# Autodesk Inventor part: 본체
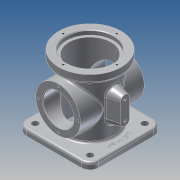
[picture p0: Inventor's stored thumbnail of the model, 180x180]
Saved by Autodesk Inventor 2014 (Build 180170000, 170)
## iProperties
Created: 2021-03
Part Number: 본체
Material: 알루미늄 6061
Document SubType Name: Modeling
Designer: kb542
Density: 2.71 g/cm^3
Appearance: 알루미늄 - 평지
Mass: 834.797 g
Surface Area: 861.783 cm^2
Volume: 308.043 cm^3
Author: kb542
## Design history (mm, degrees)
sketch "스케치1"
  geometry: L1 (0, 0)-(0, -111); L2 (0, 0)-(49, 0); L3 (49, 0)-(49, -13); L4 (49, -13)-(38, -13); L5 (38, -13)-(38, -111); L6 (38, -111)-(0, -111)
  constraints: 12 end point, 3 parallel, 2 perpendicular, 1 vertical
  dimensions: "d0" = 111 distance between parallel lines of L6 L2; "d1" = 76 diameter of L5 L1; "d2" = 98 diameter of L3 L1; "d3" = 13 distance between parallel lines of L4 L2
revolve "회전1" sketch "스케치1" stored, may be unused: angle "d4" = 90 deg
sketch "스케치2"
  geometry: L1 (-57, 57)-(57, 57); L2 (57, 57)-(57, -57); L3 (57, -57)-(-57, -57); L4 (-57, -57)-(-57, 57); C1 r 38 at (0, 0) reference; 2 further points
  constraints: 8 end point, 2 midpoint, 2 parallel, 1 horizontal, 1 horizontal alignment, 1 perpendicular, 1 vertical alignment
  dimensions: "d5" = 114 distance of L1.start L1.end; "d6" = 114 distance of L1.end L2.end
extrude "돌출1" join sketch "스케치2" distance "d7" = 10; taper "d8" = 0 deg
sketch "스케치3"
  geometry: L1 (-49, 0)-(49, 0) reference; L2 (57, -111)-(-57, -111) reference; L3 (0, 0)-(0, -111); L4 (0, 0)-(37, 0); L5 (37, 0)-(37, -7); L6 (37, -7)-(33, -7); L7 (33, -7)-(33, -111); L8 (33, -111)-(0, -111)
  constraints: 12 end point, 2 perpendicular, 2 point on line, 1 collinear, 1 midpoint, 1 parallel
  dimensions: "d9" = 74 diameter of L5 L3; "d10" = 66 diameter of L7 L3; "d11" = 7 distance between parallel lines of L1 L6
revolve "회전2" sketch "스케치3" stored, may be unused: angle "d12" = 90 deg
node "작업 평면1"
sketch "스케치4"
  geometry: L1 (0, 49)-(0, -49) reference; L2 (-111, 57)-(-111, -57) reference; L3 (-13, 38)-(-101, 38) reference; L4 (-13, -38)-(-101, -38) reference; L5 (-57, 38)-(-57, -38); L6 (0, 0)-(-111, 0); C1 r 35 at (-57, 0)
  constraints: 4 end point, 4 midpoint, 1 centre point, 1 perpendicular, 1 point on line
  dimensions: "d14" = 54 distance between parallel lines of L2 L5; "d15" = 70 diameter of C1
extrude "돌출2" join sketch "스케치4" stored distance "d16" = 10; taper "d17" = 0 deg
sketch "스케치5"
  geometry: C1 r 35 at (0, 0) reference; C2 r 24 at (0, 0); 1 further point
  constraints: 1 centre point, 1 coincident
  dimensions: "d18" = 48 diameter of C2
extrude "돌출3" cut sketch "스케치5" stored distance "d19" = 10; taper "d20" = 0 deg
sketch "스케치6" dims "d21" = 62
  geometry: C1 r 24 at (0, 0) reference; C2 r 35 at (0, 0) reference; 6 further points
  constraints: 2 vertical alignment, 1 coincident, 7 other
  dimensions: "d24" = 360 deg dimension on C1.centre point (0, 31) (derived)
hole "구멍1" sketch "스케치6" at (0, 31), (-31, 0), (0, -31), (31, 0) diameter "d26" = 3.242; stored, may be unused: countersink angle "d30" = 90 deg, drill point angle "d32" = 118 deg; dims "d27" = 6, "d28" = 4, "d29" = 2, "d31" = 8
fillet "모깎기1" dims "d33" = 14
sketch "스케치7"
  geometry: A1 r 14 centre (43, 43) between (57, 43) and (43, 57) reference; A2 r 14 centre (-43, 43) between (-43, 57) and (-57, 43) reference; A3 r 14 centre (-43, -43) between (-57, -43) and (-43, -57) reference; A4 r 14 centre (43, -43) between (43, -57) and (57, -43) reference; 4 further points
  constraints: 4 coincident
hole "구멍2" sketch "스케치7" at (-43, 43), (43, 43), (43, -43), (-43, -43) diameter "d34" = 10; stored, may be unused: countersink angle "d38" = 90 deg, drill point angle "d40" = 0 deg; dims "d35" = 6, "d36" = 4, "d37" = 2, "d39" = 8
node "작업 평면3"
sketch "스케치8"
  geometry: L1 (-50, -22)-(-50, -92) reference; L2 (50, -22)-(50, -92) reference; L3 (-50, -57)-(50, -57); L4 (0, -41)-(0, -70); L5 (-7, -41)-(-7, -70); L6 (7, -70)-(7, -41); A1 r 7 centre (0, -41) between (7, -41) and (-7, -41); A2 r 7 centre (0, -70) between (-7, -70) and (7, -70); 3 further points
  constraints: 10 end point, 4 midpoint, 4 point on circle, 4 tangent, 2 centre point, 1 parallel, 1 perpendicular, 1 vertical alignment
  dimensions: "d42" = 43 dimension on A2 A1; "d43" = 14 distance between parallel lines of L5 L6; "d44" = 20 dimension on A2 L3
extrude "돌출4" join sketch "스케치8" stored distance "d45" = 10; taper "d46" = 15 deg
sketch "스케치9"
  geometry: A1 r 7 centre (0, -70) between (-7, -70) and (7, -70) reference; A2 r 7 centre (0, -41) between (7, -41) and (-7, -41) reference; 3 further points
  constraints: 2 coincident
hole "구멍3" sketch "스케치9" at (0, -41), (0, -70) diameter "d47" = 4.134; stored, may be unused: countersink angle "d51" = 90 deg, drill point angle "d53" = 118 deg; dims "d48" = 8, "d49" = 4, "d50" = 2, "d52" = 10
sketch "스케치10"
  geometry: C1 r 38 at (0, 0) reference; C2 r 50 at (0, 0)
  constraints: 1 centre point, 1 coincident, 1 other
  dimensions: "d54" = 100 diameter of C2
feature "엠보싱1" sketch "스케치10" dims "d0" = 111, "d1" = 76, "d2" = 98, "d3" = 13, "d55" = 1, "d56" = 0
fillet "모깎기2" dims "d57" = 3
chamfer "모따기1" distance "d58" = 1; stored, may be unused: second distance "d59" = 2, angle "d60" = 45 deg
sketch "스케치11" dims "d61" = 84
  geometry: C1 r 49 at (0, 0) reference; C2 r 38 at (0, 0) reference; 5 further points
  constraints: 2 vertical alignment, 1 coincident, 7 other
  dimensions: "d64" = 360 deg dimension on C1.centre point (0, 42) (derived)
hole "구멍4" sketch "스케치11" at (0, 42), (-42, 0), (0, -42), (42, 0) diameter "d66" = 3.242; stored, may be unused: countersink angle "d70" = 90 deg, drill point angle "d72" = 118 deg; dims "d67" = 6, "d68" = 4, "d69" = 2, "d71" = 8
node "솔리드1"
mirror "대칭1"
mirror "대칭2"
node "작업 평면2"
other parameters: "d41" = 55
